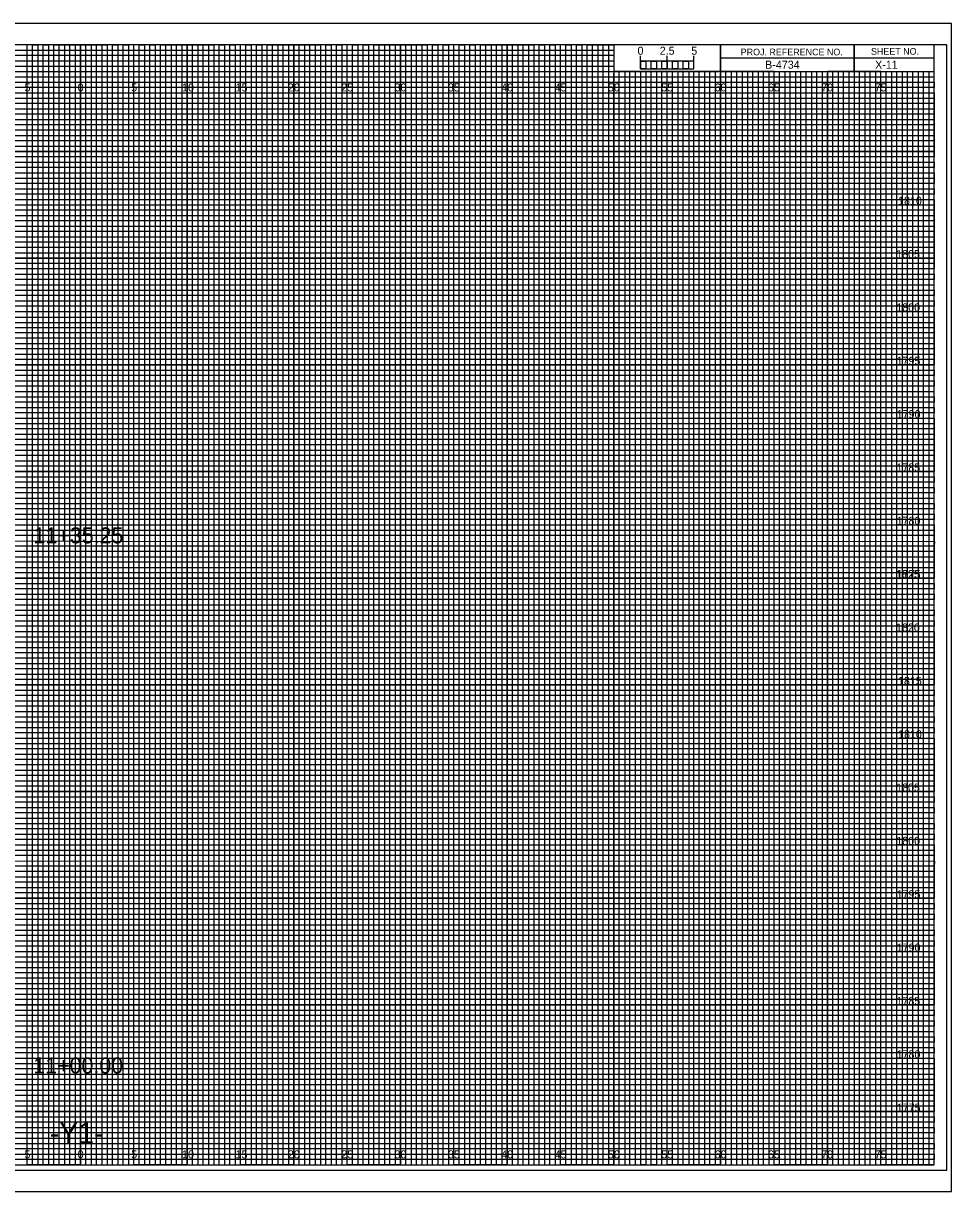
# Model space of a CAD drawing. Extents: x -7 to 162, y -2 to 107.
# Drawn here: x 74.6 to 161.7, y -2.5 to 107 of the extents above; entities that cross this region are included whole.
import ezdxf

# ---------------------------------------------------------------- set-up
doc = ezdxf.new("R2010")
doc.units = 0
for name, color, linetype in [('Prop XS Alignment Label', 7, 'Continuous'), ('Prop XS Bar Scale Labels', 7, 'Continuous'), ('Prop XS Elevation Labels', 7, 'Continuous'), ('Prop XS Offset Labels', 7, 'Continuous'), ('Prop XS Project Number', 7, 'Continuous'), ('Prop XS Sheet Number', 7, 'Continuous'), ('Prop XS Station Labels', 7, 'Continuous'), ('Sheet Cross Section CELL', 7, 'Continuous'), ('Sheet Cross Section Grid Major CELL', 7, 'Continuous'), ('Sheet Cross Section Grid Middle CELL', 7, 'Continuous'), ('Sheet Cross Section Grid Minor 1 CELL', 7, 'Continuous'), ('Sheet Cross Section Grid Minor 2 CELL', 7, 'Continuous'), ('Sheet Cross Section Scale CELL', 7, 'Continuous'), ('Sheet Cutting Line CELL', 7, 'Continuous'), ('Sheet DOT Grid CELL', 7, 'Continuous'), ('Sheet Plot Border Inside CELL', 7, 'Continuous'), ('Sheet Plot Border Outside CELL', 7, 'Continuous')]:
    doc.layers.add(name, color=color, linetype=linetype)

msp = doc.modelspace()

# ---------------------------------------------------------------- linework, layer by layer
at = {"layer": 'Sheet Cross Section CELL'}
for p, q in [((152.5, 105), (152.5, 102.5)), ((152.5, 102.5), (152.5, 105)), ((160, 103.75), (140, 103.75)), ((140, 103.75), (140, 102.5)), ((140, 102.5), (160, 102.5))]:
    msp.add_line(p, q, dxfattribs=at)
for points in [[(160, 105), (0, 105), (0, 0), (160, 0)], [(140, 105), (130, 105), (130, 102.52), (140, 102.52)], [(160, 105), (140, 105), (140, 102.5), (160, 102.5)]]:
    msp.add_lwpolyline(points, close=True, dxfattribs=at)
at = {"layer": 'Sheet Cross Section Grid Major CELL'}
for p, q in [((75, 105), (70, 105)), ((75, 0), (75, 105)), ((85, 105), (80, 105)), ((80, 105), (80, 0)), ((85, 0), (85, 105)), ((95, 105), (90, 105)), ((90, 105), (90, 0)), ((95, 0), (95, 105)), ((105, 105), (100, 105)), ((100, 105), (100, 0)), ((105, 0), (105, 105)), ((115, 105), (110, 105)), ((110, 105), (110, 0)), ((115, 0), (115, 105)), ((125, 105), (120, 105)), ((120, 105), (120, 0)), ((125, 0), (125, 105)), ((130, 105), (130, 0)), ((135, 0), (135, 102.5)), ((145, 102.5), (140, 102.5)), ((140, 102.5), (140, 0)), ((145, 0), (145, 102.5)), ((155, 102.5), (150, 102.5)), ((150, 102.5), (150, 0)), ((155, 0), (155, 102.5)), ((80, 0), (75, 0)), ((90, 0), (85, 0)), ((100, 0), (95, 0)), ((110, 0), (105, 0)), ((120, 0), (115, 0)), ((130, 0), (125, 0)), ((140, 0), (135, 0)), ((150, 0), (145, 0)), ((160, 0), (155, 0)), ((160, 0), (160, 0))]:
    msp.add_line(p, q, dxfattribs=at)
for points in [[(0, 100), (160, 100), (160, 95), (0, 95)], [(0, 90), (160, 90), (160, 85), (0, 85)], [(0, 80), (160, 80), (160, 75), (0, 75)], [(0, 70), (160, 70), (160, 65), (0, 65)], [(0, 60), (160, 60), (160, 55), (0, 55)], [(0, 50), (160, 50), (160, 45), (0, 45)], [(0, 40), (160, 40), (160, 35), (0, 35)], [(0, 30), (160, 30), (160, 25), (0, 25)], [(0, 20), (160, 20), (160, 15), (0, 15)], [(0, 10), (160, 10), (160, 5), (0, 5)]]:
    msp.add_lwpolyline(points, dxfattribs=at)
at = {"layer": 'Sheet Cross Section Grid Middle CELL'}
for points in [[(72.5, 0), (77.5, 0), (77.5, 105), (82.5, 105), (82.5, 0), (87.5, 0), (87.5, 105), (92.5, 105), (92.5, 0), (97.5, 0), (97.5, 105), (102.5, 105), (102.5, 0), (107.5, 0), (107.5, 105), (112.5, 105), (112.5, 0), (117.5, 0), (117.5, 105), (122.5, 105), (122.5, 0), (127.5, 0), (127.5, 105), (129.97, 105), (130, 105), (130, 102.5), (132.5, 102.5), (132.5, 0), (137.5, 0), (137.5, 102.5), (142.5, 102.5), (142.5, 0), (147.5, 0), (147.5, 102.5), (152.5, 102.5), (152.5, 0), (157.5, 0), (157.5, 102.5)], [(0, 102.5), (137.5, 102.5)], [(0, 92.5), (160, 92.5), (160, 97.5), (0, 97.5)], [(0, 82.5), (160, 82.5), (160, 87.5), (0, 87.5)], [(0, 72.5), (160, 72.5), (160, 77.5), (0, 77.5)], [(0, 62.5), (160, 62.5), (160, 67.5), (0, 67.5)], [(0, 52.5), (160, 52.5), (160, 57.5), (0, 57.5)], [(0, 42.5), (160, 42.5), (160, 47.5), (0, 47.5)], [(0, 32.5), (160, 32.5), (160, 37.5), (0, 37.5)], [(0, 22.5), (160, 22.5), (160, 27.5), (0, 27.5)], [(0, 12.5), (160, 12.5), (160, 17.5), (0, 17.5)], [(0, 2.5), (160, 2.5), (160, 7.5), (0, 7.5)]]:
    msp.add_lwpolyline(points, dxfattribs=at)
at = {"layer": 'Sheet Cross Section Grid Minor 1 CELL'}
for p, q in [((0, 104.5), (130, 104.5)), ((130, 104.5), (130, 103.99)), ((130, 103.99), (0, 103.99)), ((0, 103.5), (130, 103.5)), ((130, 102.95), (0, 102.95)), ((130, 103.5), (130, 102.95)), ((0, 102), (160, 102))]:
    msp.add_line(p, q, dxfattribs=at)
for points in [[(0, 101.5), (135, 101.5), (160, 101.5), (160, 101), (0, 101)], [(0, 100.5), (160, 100.5), (160, 99.5), (0, 99.5)], [(0, 99), (160, 99), (160, 98.5), (0, 98.49)], [(0, 98), (160, 98), (160, 97), (0, 97)], [(0, 96.5), (160, 96.5), (160, 96), (0, 96)], [(0, 95.5), (160, 95.5), (160, 94.5), (0, 94.5)], [(0, 94), (160, 94), (160, 93.5), (0, 93.5)], [(0, 93), (160, 93), (160, 92), (0, 92)], [(0, 91.5), (160, 91.5), (160, 91), (0, 91)], [(0, 90.5), (160, 90.5), (160, 89.5), (0, 89.5)], [(0, 89), (160, 89), (160, 88.5), (0, 88.5)], [(0, 88), (160, 88), (160, 86.98), (160, 86.5), (160, 86), (0, 86)], [(0, 87), (160, 87), (160, 86.5), (0, 86.5)], [(0, 85.5), (160, 85.5), (160, 84.5), (0, 84.52)], [(0, 84.52), (160, 84.5), (160, 84), (0, 84)], [(0, 83.5), (160, 83.5), (160, 83), (0, 83)], [(0, 82), (160, 82), (160, 81.5), (0, 81.5)], [(0, 81), (160, 81), (160, 80.5), (0, 80.5)], [(-0.04, 79.45), (160, 79.45), (160, 78.94), (-0.04, 78.94)], [(0, 78.5), (160, 78.5), (160, 78), (0, 78)], [(0, 77), (160, 77), (160, 76.5), (0, 76.5)], [(0, 76), (160, 76), (160, 75.5), (0, 75.5)], [(0, 74.5), (160, 74.5), (160, 74), (0, 74)], [(0, 73.5), (160, 73.5), (160, 73), (0, 73)], [(0, 72), (160, 72), (160, 71.5), (0, 71.5)], [(0, 71), (160, 71), (160, 70.5), (0, 70.5)], [(0, 69.5), (160, 69.5), (160, 68.99), (0, 69)], [(0, 68.5), (160, 68.5), (160, 68), (0, 68)], [(0, 67), (160, 67), (160, 66.5), (0, 66.5)], [(0, 66), (160, 66), (160, 65.5), (0, 65.5)], [(0, 64.5), (160, 64.5), (160, 64), (0, 64)], [(0, 63.5), (160, 63.5), (160, 63), (0, 63)], [(0, 62), (160, 62), (160, 61.5), (0, 61.5)], [(0, 61), (160, 61), (160, 60.5), (0, 60.5)], [(0, 59.5), (160, 59.5), (160, 59), (0, 59)], [(0, 58.5), (160.03, 58.45), (160, 58), (0, 58)], [(0, 57), (160, 57), (160, 56.5), (0, 56.5)], [(0, 56), (160, 56), (160, 55.5), (0, 55.5)], [(0, 54.5), (160, 54.5), (160, 54), (0, 54)], [(0, 53.5), (160, 53.5), (160, 53), (0, 53)], [(0, 52), (160, 52), (160, 51.5), (0, 51.5)], [(0, 51), (160, 51), (160, 50.5), (0, 50.5)], [(0, 49.5), (160, 49.5), (160, 49), (0, 49)], [(0, 48.5), (160, 48.5), (160, 48), (0, 48)], [(0, 47), (160, 47), (160, 46.5), (0, 46.5)], [(0, 46), (160, 46), (160, 45.5), (0, 45.5)], [(0, 44.5), (160, 44.5), (160, 44), (0, 44)], [(0, 43.5), (160, 43.5), (160, 43), (0, 43)], [(0, 42), (160, 42), (160, 41.5), (0, 41.5)], [(0, 41), (160, 41), (160, 40.5), (0, 40.5)], [(0, 39.5), (160, 39.5), (160, 38.99), (0, 39)], [(0, 38.5), (160, 38.5), (160, 38), (0, 38)], [(0, 37), (160, 37), (160, 36.5), (0, 36.5)], [(0, 36), (160, 36), (160, 35.5), (0, 35.5)], [(0, 34.5), (160, 34.5), (160, 34), (0, 34)], [(0, 33.5), (160, 33.5), (160, 33), (0, 33)], [(0, 32), (160, 32), (160, 31.5), (0, 31.5)], [(0, 31), (160, 31), (160, 30.5), (0, 30.5)], [(0, 29.5), (160, 29.5), (160, 29), (0, 29)], [(0, 28.5), (160.03, 28.46), (160, 28), (0, 28)], [(0, 27), (160, 27), (160, 26.5), (0, 26.5)], [(0, 26), (160, 26), (160, 25.5), (0, 25.5)], [(0, 24.5), (160, 24.5), (160, 24), (0, 24)], [(0, 23.5), (160, 23.5), (160, 23), (0, 23)], [(0, 22), (160, 22), (160, 21.5), (0, 21.5)], [(0, 21), (160, 21), (160, 20.5), (0, 20.5)], [(0, 19.5), (160, 19.5), (160, 19), (0, 19)], [(0, 18.5), (160, 18.5), (160, 18), (0, 18)], [(0, 17), (160, 17), (160, 16.5), (0, 16.5)], [(0, 16), (160, 16), (160, 15.5), (0, 15.5)], [(0, 14.5), (160, 14.5), (160, 14), (0, 14)], [(0, 13.5), (160, 13.5), (160, 13), (0, 13)], [(0, 12), (160, 12), (160, 11.5), (0, 11.5)], [(0, 11), (160, 11), (160, 10.5), (0, 10.5)], [(0, 9.5), (160, 9.5), (160, 9), (0, 9)], [(0, 8.5), (160, 8.5), (160, 8), (0, 8)], [(0, 7), (160, 7), (160, 6.5), (0, 6.5)], [(0, 6), (160, 6), (160, 5.5), (0, 5.5)], [(0, 4.5), (160, 4.5), (160, 4), (0, 4)], [(0, 3.5), (160, 3.5), (160, 3), (0, 3)], [(0, 2), (160, 2), (160, 1.5), (0, 1.5)], [(0, 1), (160, 1), (160, 0.5), (0, 0.5)]]:
    msp.add_lwpolyline(points, dxfattribs=at)
at = {"layer": 'Sheet Cross Section Grid Minor 2 CELL'}
for p, q in [((133.5, 102.5), (133, 102.5)), ((133, 102.5), (133, 0)), ((133.5, 0), (133.5, 102.5)), ((134.5, 102.5), (134, 102.5)), ((134, 102.5), (134, 0)), ((134.5, 0), (134.5, 102.5)), ((133, 0), (132.5, 0)), ((134, 0), (133.5, 0))]:
    msp.add_line(p, q, dxfattribs=at)
for points in [[(75, 0), (75.5, 0), (75.5, 105), (76, 105), (76, 0)], [(76, 0), (76.5, 0), (76.5, 105), (77, 105), (77, 0)], [(77.5, 0), (78, 0), (78, 105), (78.5, 105), (78.5, 0)], [(78.5, 0), (79, 0), (79, 105), (79.5, 105), (79.5, 0)], [(80, 0), (80.5, 0), (80.5, 105), (81, 105), (81, 0)], [(81, 0), (81.5, 0), (81.5, 105), (82, 105), (82, 0)], [(82.5, 0), (83, 0), (83, 105), (83.5, 105), (83.5, 0)], [(83.5, 0), (84, 0), (84, 105), (84.5, 105), (84.5, 0)], [(85, 0), (85.5, 0), (85.5, 105), (86, 105), (86, 0)], [(86, 0), (86.5, 0), (86.5, 105), (87, 105), (87, 0)], [(87.5, 0), (88, 0), (88, 105), (88.5, 105), (88.5, 0)], [(88.5, 0), (89, 0), (89, 105), (89.5, 105), (89.5, 0)], [(90, 0), (90.5, 0), (90.5, 105), (91, 105), (91, 0)], [(91, 0), (91.5, 0), (91.5, 105), (92, 105), (92, 0)], [(92.5, 0), (93, 0), (93, 105), (93.5, 105), (93.5, 0)], [(93.5, 0), (94, 0), (94, 105), (94.5, 105), (94.5, 0)], [(95, 0), (95.5, 0), (95.5, 105), (96, 105), (96, 0)], [(96, 0), (96.5, 0), (96.5, 105), (97, 105), (97, 0)], [(97.5, 0), (98, 0), (98, 105), (98.5, 105), (98.5, 0)], [(98.5, 0), (99, 0), (99, 105), (99.5, 105), (99.5, 0)], [(100, 0), (100.5, 0), (100.5, 105), (101, 105), (101, 0)], [(101, 0), (101.5, 0), (101.5, 105), (102, 105), (102, 0)], [(102.5, 0), (103, 0), (103, 105), (103.5, 105), (103.5, 0)], [(103.5, 0), (104, 0), (104, 105), (104.5, 105), (104.5, 0)], [(105, 0), (105.5, 0), (105.5, 105), (106, 105), (106, 0)], [(106, 0), (106.5, 0), (106.5, 105), (107, 105), (107, 0)], [(107.5, 0), (108, 0), (108, 105), (108.5, 105), (108.5, 0)], [(108.5, 0), (109, 0), (109, 105), (109.5, 105), (109.5, 0)], [(110, 0), (110.5, 0), (110.5, 105), (111, 105), (111, 0)], [(111, 0), (111.5, 0), (111.5, 105), (112, 105), (112, 0)], [(112.5, 0), (113, 0), (113, 105), (113.5, 105), (113.5, 0)], [(113.5, 0), (114, 0), (114, 105), (114.5, 105), (114.5, 0)], [(115, 0), (115.5, 0), (115.5, 105), (116, 105), (116, 0)], [(116, 0), (116.5, 0), (116.5, 105), (117, 105), (117, 0)], [(117.5, 0), (118, 0), (118, 105), (118.5, 105), (118.5, 0)], [(118.5, 0), (119, 0), (119, 105), (119.5, 105), (119.5, 0)], [(120, 0), (120.5, 0), (120.5, 105), (121, 105), (121, 0)], [(121, 0), (121.5, 0), (121.5, 105), (122, 105), (122, 0)], [(122.5, 0), (123, 0), (123, 105), (123.5, 105), (123.5, 0)], [(123.5, 0), (124, 0), (124, 105), (124.5, 105), (124.5, 0)], [(125, 0), (125.5, 0), (125.5, 105), (126, 105), (126, 0)], [(126, 0), (126.5, 0), (126.5, 105), (127, 105), (127, 0)], [(127.5, 0), (128, 0), (128, 105), (128.5, 105), (128.5, 0)], [(128.5, 0), (129, 0), (129, 105), (129.5, 105), (129.5, 0)], [(130, 0), (130.5, 0), (130.5, 102.5), (131.01, 102.5), (131.01, 0)], [(131, 0), (131.5, 0), (131.5, 102.5), (132, 102.5), (132, 0)], [(135, 0), (135.49, 0), (135.49, 102.5), (136, 102.5), (136, 0)], [(136, 0), (136.5, 0), (136.5, 102.5), (137.03, 102.5), (137.03, 0)], [(137.5, 0), (138, 0), (138, 102.5), (138.5, 102.5), (138.5, 0)], [(138.5, 0), (139, 0), (139, 102.5), (139.5, 102.5), (139.5, 0)], [(140, 0), (140.5, 0), (140.5, 102.5), (141, 102.5), (141, 0)], [(141, 0), (141.5, 0), (141.5, 102.5), (142, 102.5), (142, 0)], [(142.5, 0), (143, 0), (143, 102.5), (143.5, 102.5), (143.5, 0)], [(143.5, 0), (144, 0), (144, 102.5), (144.5, 102.5), (144.5, 0)], [(145, 0), (145.5, 0), (145.5, 102.5), (146, 102.5), (146, 0)], [(146, 0), (146.5, 0), (146.5, 102.5), (147, 102.5), (147, 0)], [(147.5, 0), (148, 0), (148, 102.5), (148.5, 102.5), (148.5, 0)], [(148.5, 0), (149, 0), (149, 102.5), (149.5, 102.5), (149.5, 0)], [(150, 0), (150.5, 0), (150.5, 102.5), (151, 102.5), (151, 0)], [(151, 0), (151.5, 0), (151.5, 102.5), (152, 102.5), (152, 0)], [(152.5, 0), (153, 0), (153, 102.5), (153.5, 102.5), (153.5, 0)], [(153.5, 0), (154, 0), (154, 102.5), (154.5, 102.5), (154.5, 0)], [(155, 0), (155.5, 0), (155.5, 102.5), (156, 102.5), (156, 0)], [(156, 0), (156.5, 0), (156.5, 102.5), (157, 102.5), (157, 0)], [(157.5, 0), (158, 0), (158, 102.5), (158.5, 102.5), (158.5, 0)], [(158.5, 0), (159, 0), (159, 102.5), (159.5, 102.5), (159.5, 0)]]:
    msp.add_lwpolyline(points, dxfattribs=at)
at = {"layer": 'Sheet Cross Section Scale CELL'}
for p, q in [((132.5, 102.75), (132.5, 103.95)), ((132.5, 103.45), (132.5, 103.95)), ((135, 102.75), (135, 103.95)), ((137.5, 102.75), (137.5, 103.95)), ((137.5, 103.45), (137.5, 103.95))]:
    msp.add_line(p, q, dxfattribs=at)
for points in [[(137.5, 103.45), (132.5, 103.45), (132.5, 102.75), (137.5, 102.75)], [(132.5, 103.45), (133, 103.45), (133, 102.75), (132.5, 102.75)], [(133.5, 103.45), (134, 103.45), (134, 102.75), (133.5, 102.75)], [(134.5, 103.45), (135, 103.45), (135, 102.75), (134.5, 102.75)], [(135.5, 103.45), (136, 103.45), (136, 102.75), (135.5, 102.75)], [(136.5, 103.45), (137, 103.45), (137, 102.75), (136.5, 102.75)]]:
    msp.add_lwpolyline(points, close=True, dxfattribs=at)
at = {"layer": 'Sheet Cutting Line CELL'}
for p, q in [((161.65, 107), (-6.7, 107)), ((-6.7, -2.5), (161.65, -2.5))]:
    msp.add_line(p, q, dxfattribs=at)
at = {"layer": 'Sheet DOT Grid CELL'}
for p, q in [((75, 0), (75, 105)), ((80, 0), (80, 105)), ((85, 0), (85, 105)), ((90, 0), (90, 105)), ((95, 0), (95, 105)), ((100, 0), (100, 105)), ((105, 0), (105, 105)), ((110, 0), (110, 105)), ((115, 0), (115, 105)), ((120, 0), (120, 105)), ((125, 0), (125, 105)), ((130, 0), (130, 102.34)), ((135, 0), (135, 102.34)), ((140, 0), (140, 102.34)), ((145, 0), (145, 102.34)), ((150, 0), (150, 102.34)), ((155, 0), (155, 102.34)), ((0, 100), (160, 100)), ((0, 95), (160, 95)), ((0, 90), (160, 90)), ((0, 85), (160, 85)), ((0, 80), (160, 80)), ((0, 75), (160, 75)), ((0, 70), (160, 70)), ((0, 65), (160, 65)), ((0, 60), (160, 60)), ((0, 55), (160, 55)), ((0, 50), (160, 50)), ((0, 45), (160, 45)), ((0, 40), (160, 40)), ((0, 35), (160, 35)), ((0, 30), (160, 30)), ((0, 25), (160, 25)), ((0, 20), (160, 20)), ((0, 15), (160, 15)), ((0, 10), (160, 10)), ((0, 5), (160, 5))]:
    msp.add_line(p, q, dxfattribs=at)
at = {"layer": 'Sheet Plot Border Inside CELL'}
msp.add_lwpolyline([(-5.4, -0.5), (161.2, -0.5), (161.2, 105), (-5.4, 105)], close=True, dxfattribs=at)
at = {"layer": 'Sheet Plot Border Outside CELL'}
msp.add_lwpolyline([(-6.7, -2.5), (161.65, -2.5), (161.65, 107), (-6.7, 107)], close=True, dxfattribs=at)

# ---------------------------------------------------------------- texts
at = {"layer": 'Prop XS Alignment Label'}
msp.add_text('-Y1-', height=2, dxfattribs=at).set_placement((77.11, 2))
at = {"layer": 'Prop XS Bar Scale Labels'}
for s, p in [('2.5', (134.29, 104.06)), ('5', (137.24, 104.06))]:
    msp.add_text(s, height=0.75, dxfattribs=at).set_placement(p)
at = {"layer": 'Prop XS Elevation Labels'}
for s, p in [('1810', (156.63, 90)), ('1805', (156.45, 85)), ('1800', (156.46, 80)), ('1795', (156.49, 75)), ('1790', (156.5, 70)), ('1785', (156.48, 65)), ('1780', (156.49, 60)), ('1825', (156.43, 55)), ('1775', (156.51, 55)), ('1820', (156.44, 50)), ('1815', (156.62, 45)), ('1810', (156.63, 40)), ('1805', (156.45, 35)), ('1800', (156.46, 30)), ('1795', (156.49, 25)), ('1790', (156.5, 20)), ('1785', (156.48, 15)), ('1780', (156.49, 10)), ('1775', (156.51, 5))]:
    msp.add_text(s, height=0.75, dxfattribs=at).set_placement(p)
at = {"layer": 'Prop XS Offset Labels'}
for s, p in [('5', (74.74, 100.62)), ('0', (79.73, 100.62)), ('0', (79.73, 100.62)), ('5', (84.74, 100.62)), ('10', (89.52, 100.62)), ('15', (94.53, 100.62)), ('20', (99.43, 100.62)), ('25', (104.44, 100.62)), ('30', (109.43, 100.62)), ('35', (114.44, 100.62)), ('40', (119.43, 100.62)), ('45', (124.44, 100.62)), ('50', (129.43, 100.62)), ('55', (134.44, 100.62)), ('60', (139.43, 100.62)), ('65', (144.44, 100.62)), ('70', (149.43, 100.62)), ('75', (154.44, 100.62)), ('5', (74.74, 0.62)), ('0', (79.73, 0.62)), ('0', (79.73, 0.62)), ('5', (84.74, 0.62)), ('10', (89.52, 0.62)), ('15', (94.53, 0.62)), ('20', (99.43, 0.62)), ('25', (104.44, 0.62)), ('30', (109.43, 0.62)), ('35', (114.44, 0.62)), ('40', (119.43, 0.62)), ('45', (124.44, 0.62)), ('50', (129.43, 0.62)), ('55', (134.44, 0.62)), ('60', (139.43, 0.62)), ('65', (144.44, 0.62)), ('70', (149.43, 0.62)), ('75', (154.44, 0.62))]:
    msp.add_text(s, height=0.75, dxfattribs=at).set_placement(p)
at = {"layer": 'Prop XS Project Number'}
msp.add_text('B-4734', height=0.75, dxfattribs=at).set_placement((144.17, 102.75))
at = {"layer": 'Prop XS Sheet Number'}
msp.add_text('X-11', height=0.75, dxfattribs=at).set_placement((154.48, 102.75))
at = {"layer": 'Prop XS Station Labels'}
for s, p in [('11+35.25', (75.59, 58.26)), ('11+00.00', (75.57, 8.58))]:
    msp.add_text(s, height=1.5, dxfattribs=at).set_placement(p)
at = {"layer": 'Sheet Cross Section CELL'}
for s, p in [('PROJ. REFERENCE NO.', (141.88, 104)), ('SHEET NO.', (154.09, 104.06))]:
    msp.add_text(s, height=0.625, dxfattribs=at).set_placement(p)
at = {"layer": 'Sheet Cross Section Scale CELL'}
msp.add_text('0', height=0.75, dxfattribs=at).set_placement((132.21, 104.06))

doc.saveas('drawing.dxf')
